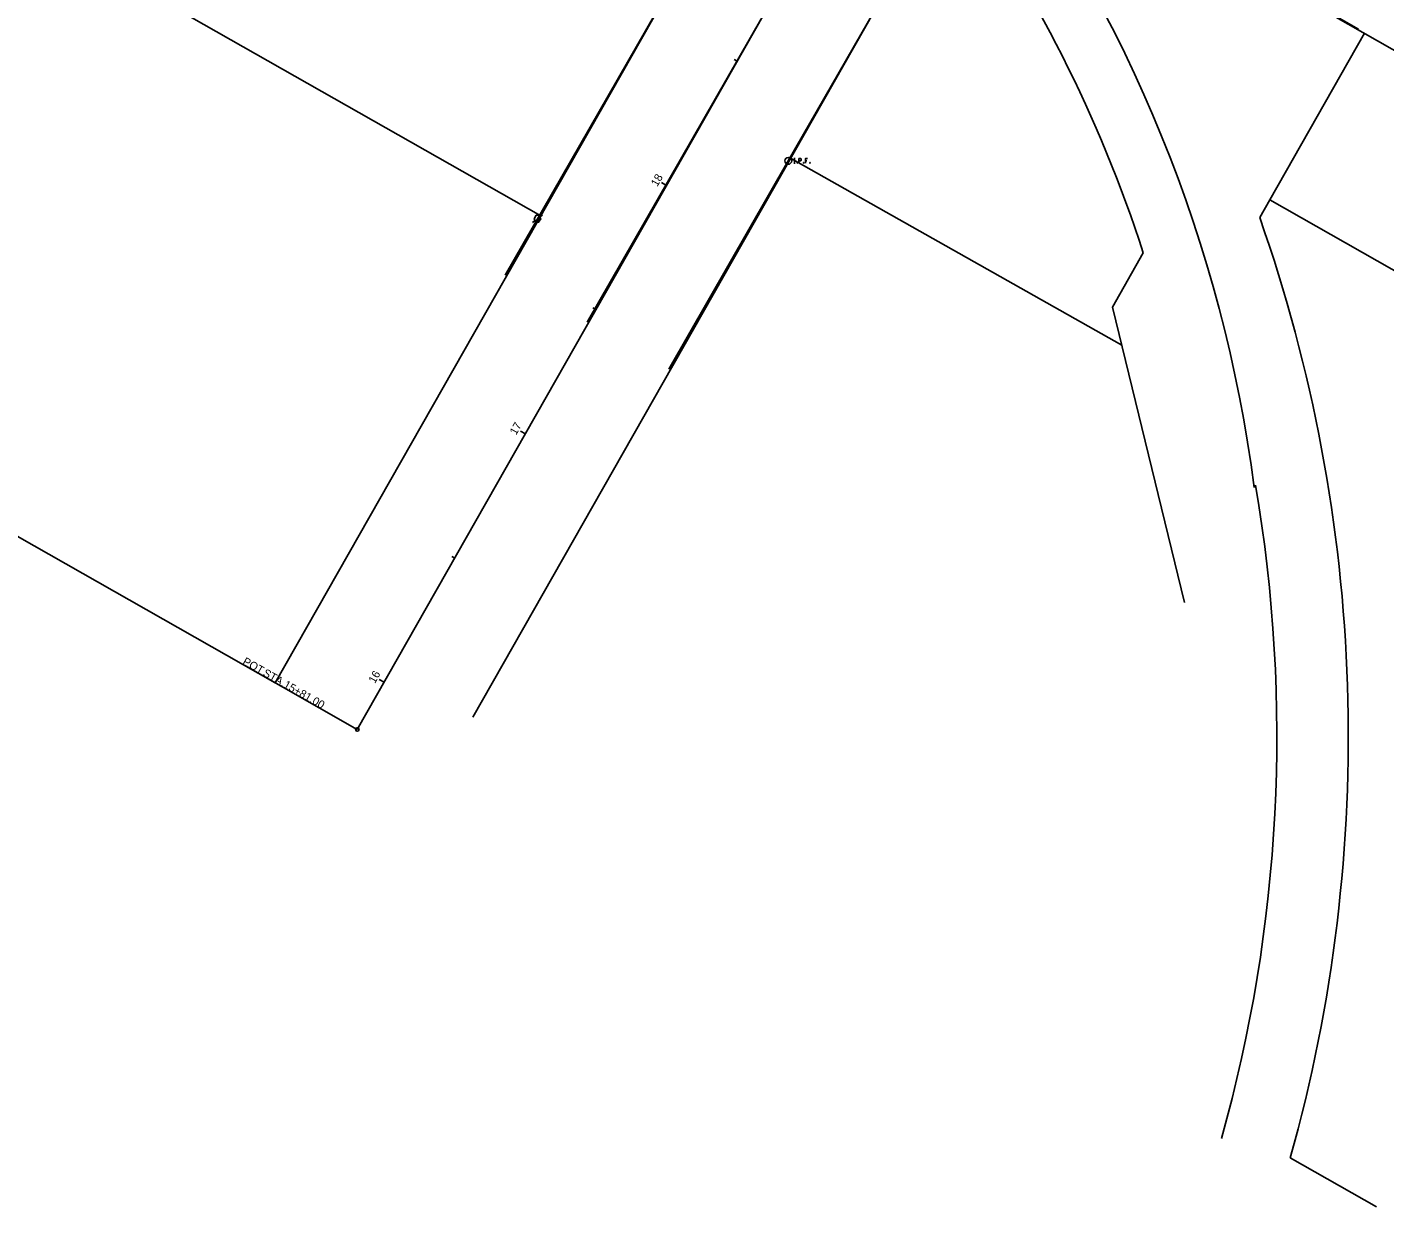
# Model space of a CAD drawing. Extents: x 119320 to 120701, y 385020 to 386199.
# Drawn here: x 119764.6 to 120239.7, y 385020.4 to 385433.2 of the extents above; entities that cross this region are included whole.
import ezdxf

# ---------------------------------------------------------------- set-up
doc = ezdxf.new("R2010")
doc.units = 0
for name, color, linetype in [('DV_X_Property_Line', 7, 'Continuous'), ('RW_X_CL', 7, 'Continuous'), ('RW_X_CL_100_Cardinal_Points', 7, 'Continuous'), ('RW_X_CL_100_Stations', 7, 'Continuous'), ('RW_X_Fee_RW', 7, 'Continuous'), ('SC_Scratch1', 7, 'Continuous'), ('SV_X_Control_Cells_Found', 7, 'Continuous'), ('SV_X_Mon_Cells_Found', 7, 'Continuous')]:
    doc.layers.add(name, color=color, linetype=linetype)

msp = doc.modelspace()

# ---------------------------------------------------------------- linework, layer by layer
at = {"layer": 'DV_X_Property_Line'}
for p, q in [((120031.77, 385387.42), (120147.7, 385321.97)), ((120199.48, 385372.85), (120195.93, 385366.6)), ((120155.19, 385354.27), (120144.47, 385335.28)), ((120144.47, 385335.28), (120169.59, 385231.83)), ((120206.63, 385037.5), (120236.77, 385020.37))]:
    msp.add_line(p, q, dxfattribs=at)
for points in [[(119944.36, 385367.19), (119772.22, 385465.04), (119870.07, 385637.17)], [(120291.71, 385397.5), (120258.44, 385339.34), (120199.48, 385372.85), (120232.59, 385431.1)]]:
    msp.add_lwpolyline(points, dxfattribs=at)
for centre, radius, start, end in [((119703.54, 385208.72), 494.53, 7.3661, 36.9032), ((119703.54, 385208.72), 474.53, 17.8628, 35.8499), ((119680.27, 385185.12), 546.67, 344.3341, 19.3891), ((119680.27, 385185.12), 521.67, 344.3341, 9.6974)]:
    msp.add_arc(centre, radius, start, end, dxfattribs=at)
at = {"layer": 'RW_X_CL'}
msp.add_line((119880.14, 385187.44), (120299.2, 385924.66), dxfattribs=at)
at = {"layer": 'RW_X_CL_100_Cardinal_Points'}
msp.add_line((119880.14, 385187.44), (119841.02, 385209.68), dxfattribs=at)
msp.add_circle((119880.14, 385187.44), 0.6, dxfattribs=at)
at = {"layer": 'RW_X_CL_100_Stations'}
for p, q in [((120013.07, 385421.3), (120012.03, 385421.9)), ((119988.37, 385377.83), (119986.63, 385378.82)), ((119963.66, 385334.37), (119962.61, 385334.96)), ((119938.95, 385290.9), (119937.21, 385291.89)), ((119914.24, 385247.43), (119913.2, 385248.02)), ((119889.53, 385203.96), (119887.79, 385204.95))]:
    msp.add_line(p, q, dxfattribs=at)
at = {"layer": 'RW_X_Fee_RW'}
for points in [[(119507.18, 385399.44), (119697.94, 385735.02), (120042.2, 385539.33), (119851.45, 385203.75), (119507.18, 385399.44)], [(119920.57, 385191.78), (120099.58, 385506.71), (120443.85, 385311.02), (120394.43, 385224.08)]]:
    msp.add_lwpolyline(points, dxfattribs=at)
at = {"layer": 'SC_Scratch1'}
for p, q in [((119960.53, 385330), (120087.8, 385551.87)), ((119931.9, 385346.42), (120042.8, 385539.75)), ((120030.95, 385386.44), (120100.05, 385506.91)), ((120100.05, 385506.91), (120230.56, 385432.57)), ((119989.15, 385313.58), (120030.95, 385386.44))]:
    msp.add_line(p, q, dxfattribs=at)
at = {"layer": 'SV_X_Control_Cells_Found'}
for p, q in [((119942.36, 385365.58), (119941.4, 385364.86)), ((119944.93, 385367.5), (119943.97, 385366.78))]:
    msp.add_line(p, q, dxfattribs=at)
msp.add_lwpolyline([(119942.71, 385367.38), (119943.61, 385367.38), (119944.32, 385366.18), (119943.61, 385364.98), (119942.71, 385364.98), (119942, 385366.18)], close=True, dxfattribs=at)
at = {"layer": 'SV_X_Mon_Cells_Found'}
for points in [[(120032.96, 385387.24), (120033.32, 385387.24)], [(120032.96, 385385.64), (120033.32, 385385.64)], [(120033.14, 385385.64), (120033.14, 385387.24)], [(120034.1, 385385.86), (120034.15, 385385.86), (120034.19, 385385.83), (120034.22, 385385.78), (120034.22, 385385.72), (120034.19, 385385.67), (120034.15, 385385.64), (120034.1, 385385.64), (120034.07, 385385.67), (120034.03, 385385.72), (120034.03, 385385.78), (120034.07, 385385.83), (120034.1, 385385.86)], [(120034.71, 385385.64), (120034.71, 385387.24), (120035.23, 385387.24), (120035.29, 385387.23), (120035.37, 385387.21), (120035.4, 385387.18), (120035.43, 385387.15), (120035.48, 385387.09), (120035.51, 385387.03), (120035.53, 385386.93), (120035.53, 385386.78), (120035.52, 385386.73), (120035.5, 385386.65), (120035.45, 385386.56), (120035.41, 385386.52), (120035.38, 385386.5), (120035.32, 385386.47), (120035.23, 385386.46), (120034.71, 385386.46)], [(120036.35, 385385.86), (120036.4, 385385.86), (120036.44, 385385.83), (120036.47, 385385.78), (120036.47, 385385.72), (120036.44, 385385.67), (120036.4, 385385.64), (120036.35, 385385.64), (120036.31, 385385.67), (120036.28, 385385.72), (120036.28, 385385.78), (120036.31, 385385.83), (120036.35, 385385.86)], [(120037.71, 385387.24), (120036.95, 385387.24), (120036.95, 385385.64)], [(120036.95, 385386.46), (120037.49, 385386.46)], [(120038.5, 385385.86), (120038.55, 385385.86), (120038.59, 385385.83), (120038.62, 385385.78), (120038.62, 385385.72), (120038.59, 385385.67), (120038.55, 385385.64), (120038.5, 385385.64), (120038.46, 385385.67), (120038.43, 385385.72), (120038.43, 385385.78), (120038.46, 385385.83), (120038.5, 385385.86)]]:
    msp.add_lwpolyline(points, dxfattribs=at)
msp.add_circle((120030.95, 385386.44), 1.2, dxfattribs=at)

# ---------------------------------------------------------------- texts
at = {"layer": 'RW_X_CL_100_Cardinal_Points'}
for s, p in [('POT', (119839.75, 385210.45)), (' STA. ', (119845.95, 385206.92)), ('15+81.00', (119854.05, 385202.32))]:
    msp.add_text(s, height=2.8, rotation=330.3847, dxfattribs=at).set_placement(p)
at = {"layer": 'RW_X_CL_100_Stations'}
for s, p in [('18', (119985.14, 385377.22)), ('17', (119935.72, 385290.29)), ('16', (119886.3, 385203.34))]:
    msp.add_text(s, height=2.8, rotation=60.3847, dxfattribs=at).set_placement(p)

doc.saveas('drawing.dxf')
